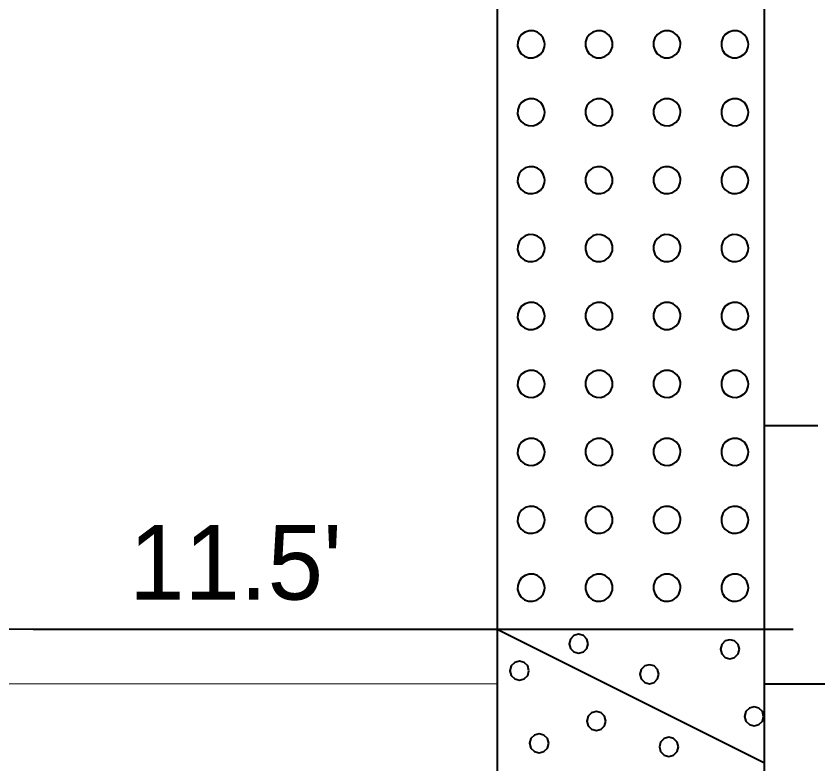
# Model space of a CAD drawing. Extents: x -76 to 974, y -1080 to -735.
# Drawn here: x 281.69 to 289.19, y -942.84 to -935.85 of the extents above; entities that cross this region are included whole.
import ezdxf

# ---------------------------------------------------------------- set-up
doc = ezdxf.new("R2010")
doc.units = 0
doc.header["$LTSCALE"] = 0.36
doc.linetypes.add('LONG_DASHED', pattern=[7.5, 6, -1.5])
for name, color, linetype, lineweight in [('27', 7, 'Continuous', 40), ('28', 7, 'LONG_DASHED', 60), ('7', 7, 'Continuous', 13)]:
    doc.layers.add(name, color=color, linetype=linetype, lineweight=lineweight)

msp = doc.modelspace()

# ---------------------------------------------------------------- linework, layer by layer
at = {"layer": '27'}
for p, q in [((286.1855, -930.0789), (286.1855, -941.5789)), ((288.6855, -941.5789), (288.6855, -930.0789)), ((289.1855, -939.6789), (288.6855, -939.6789)), ((282.4181, -941.5789), (286.1855, -941.5789)), ((286.1855, -941.5789), (288.6855, -941.5789)), ((286.1855, -941.5789), (288.6855, -942.8289)), ((286.1855, -941.5789), (286.1855, -947.0789)), ((288.6855, -947.0789), (288.6855, -941.5789)), ((288.6855, -942.09), (321.1855, -942.09))]:
    msp.add_line(p, q, dxfattribs=at)
for points in [[(286.6301, -936.1114), (286.6286, -936.0917), (286.6164, -936.054), (286.5933, -936.0219), (286.5614, -935.9985), (286.5239, -935.986), (286.4843, -935.9857), (286.4466, -935.9975), (286.4143, -936.0204), (286.3906, -936.0521), (286.3778, -936.0895), (286.3771, -936.129), (286.3886, -936.1669), (286.4112, -936.1994), (286.4426, -936.2233), (286.4799, -936.2365), (286.5195, -936.2375), (286.5574, -936.2263), (286.5901, -936.204), (286.6143, -936.1728), (286.6278, -936.1356)], [(287.2651, -936.1114), (287.2636, -936.0917), (287.2514, -936.054), (287.2283, -936.0219), (287.1964, -935.9985), (287.1589, -935.986), (287.1193, -935.9857), (287.0816, -935.9975), (287.0493, -936.0204), (287.0256, -936.0521), (287.0128, -936.0895), (287.0121, -936.129), (287.0236, -936.1669), (287.0462, -936.1994), (287.0776, -936.2233), (287.1149, -936.2365), (287.1545, -936.2375), (287.1924, -936.2263), (287.2251, -936.204), (287.2493, -936.1728), (287.2628, -936.1356)], [(287.9001, -936.1114), (287.8986, -936.0917), (287.8864, -936.054), (287.8633, -936.0219), (287.8314, -935.9985), (287.7939, -935.986), (287.7543, -935.9857), (287.7166, -935.9975), (287.6843, -936.0204), (287.6606, -936.0521), (287.6478, -936.0895), (287.6471, -936.129), (287.6586, -936.1669), (287.6812, -936.1994), (287.7126, -936.2233), (287.7499, -936.2365), (287.7895, -936.2375), (287.8274, -936.2263), (287.8601, -936.204), (287.8843, -936.1728), (287.8978, -936.1356)], [(288.5351, -936.1114), (288.5336, -936.0917), (288.5214, -936.054), (288.4983, -936.0219), (288.4664, -935.9985), (288.4289, -935.986), (288.3893, -935.9857), (288.3516, -935.9975), (288.3193, -936.0204), (288.2956, -936.0521), (288.2828, -936.0895), (288.2821, -936.129), (288.2936, -936.1669), (288.3162, -936.1994), (288.3476, -936.2233), (288.3849, -936.2365), (288.4245, -936.2375), (288.4624, -936.2263), (288.4951, -936.204), (288.5193, -936.1728), (288.5328, -936.1356)], [(286.6301, -936.7464), (286.6286, -936.7267), (286.6164, -936.689), (286.5933, -936.6569), (286.5614, -936.6335), (286.5239, -936.621), (286.4843, -936.6207), (286.4466, -936.6325), (286.4143, -936.6554), (286.3906, -936.6871), (286.3778, -936.7245), (286.3771, -936.764), (286.3886, -936.8019), (286.4112, -936.8344), (286.4426, -936.8583), (286.4799, -936.8715), (286.5195, -936.8725), (286.5574, -936.8613), (286.5901, -936.839), (286.6143, -936.8078), (286.6278, -936.7706)], [(287.2651, -936.7464), (287.2636, -936.7267), (287.2514, -936.689), (287.2283, -936.6569), (287.1964, -936.6335), (287.1589, -936.621), (287.1193, -936.6207), (287.0816, -936.6325), (287.0493, -936.6554), (287.0256, -936.6871), (287.0128, -936.7245), (287.0121, -936.764), (287.0236, -936.8019), (287.0462, -936.8344), (287.0776, -936.8583), (287.1149, -936.8715), (287.1545, -936.8725), (287.1924, -936.8613), (287.2251, -936.839), (287.2493, -936.8078), (287.2628, -936.7706)], [(287.9001, -936.7464), (287.8986, -936.7267), (287.8864, -936.689), (287.8633, -936.6569), (287.8314, -936.6335), (287.7939, -936.621), (287.7543, -936.6207), (287.7166, -936.6325), (287.6843, -936.6554), (287.6606, -936.6871), (287.6478, -936.7245), (287.6471, -936.764), (287.6586, -936.8019), (287.6812, -936.8344), (287.7126, -936.8583), (287.7499, -936.8715), (287.7895, -936.8725), (287.8274, -936.8613), (287.8601, -936.839), (287.8843, -936.8078), (287.8978, -936.7706)], [(288.5351, -936.7464), (288.5336, -936.7267), (288.5214, -936.689), (288.4983, -936.6569), (288.4664, -936.6335), (288.4289, -936.621), (288.3893, -936.6207), (288.3516, -936.6325), (288.3193, -936.6554), (288.2956, -936.6871), (288.2828, -936.7245), (288.2821, -936.764), (288.2936, -936.8019), (288.3162, -936.8344), (288.3476, -936.8583), (288.3849, -936.8715), (288.4245, -936.8725), (288.4624, -936.8613), (288.4951, -936.839), (288.5193, -936.8078), (288.5328, -936.7706)], [(286.6301, -937.3814), (286.6286, -937.3617), (286.6164, -937.324), (286.5933, -937.2919), (286.5614, -937.2685), (286.5239, -937.256), (286.4843, -937.2557), (286.4466, -937.2675), (286.4143, -937.2904), (286.3906, -937.3221), (286.3778, -937.3595), (286.3771, -937.399), (286.3886, -937.4369), (286.4112, -937.4694), (286.4426, -937.4933), (286.4799, -937.5065), (286.5195, -937.5075), (286.5574, -937.4963), (286.5901, -937.474), (286.6143, -937.4428), (286.6278, -937.4056)], [(287.2651, -937.3814), (287.2636, -937.3617), (287.2514, -937.324), (287.2283, -937.2919), (287.1964, -937.2685), (287.1589, -937.256), (287.1193, -937.2557), (287.0816, -937.2675), (287.0493, -937.2904), (287.0256, -937.3221), (287.0128, -937.3595), (287.0121, -937.399), (287.0236, -937.4369), (287.0462, -937.4694), (287.0776, -937.4933), (287.1149, -937.5065), (287.1545, -937.5075), (287.1924, -937.4963), (287.2251, -937.474), (287.2493, -937.4428), (287.2628, -937.4056)], [(287.9001, -937.3814), (287.8986, -937.3617), (287.8864, -937.324), (287.8633, -937.2919), (287.8314, -937.2685), (287.7939, -937.256), (287.7543, -937.2557), (287.7166, -937.2675), (287.6843, -937.2904), (287.6606, -937.3221), (287.6478, -937.3595), (287.6471, -937.399), (287.6586, -937.4369), (287.6812, -937.4694), (287.7126, -937.4933), (287.7499, -937.5065), (287.7895, -937.5075), (287.8274, -937.4963), (287.8601, -937.474), (287.8843, -937.4428), (287.8978, -937.4056)], [(288.5351, -937.3814), (288.5336, -937.3617), (288.5214, -937.324), (288.4983, -937.2919), (288.4664, -937.2685), (288.4289, -937.256), (288.3893, -937.2557), (288.3516, -937.2675), (288.3193, -937.2904), (288.2956, -937.3221), (288.2828, -937.3595), (288.2821, -937.399), (288.2936, -937.4369), (288.3162, -937.4694), (288.3476, -937.4933), (288.3849, -937.5065), (288.4245, -937.5075), (288.4624, -937.4963), (288.4951, -937.474), (288.5193, -937.4428), (288.5328, -937.4056)], [(286.6301, -938.0164), (286.6286, -937.9967), (286.6164, -937.959), (286.5933, -937.9269), (286.5614, -937.9035), (286.5239, -937.891), (286.4843, -937.8907), (286.4466, -937.9025), (286.4143, -937.9254), (286.3906, -937.9571), (286.3778, -937.9945), (286.3771, -938.034), (286.3886, -938.0719), (286.4112, -938.1044), (286.4426, -938.1283), (286.4799, -938.1415), (286.5195, -938.1425), (286.5574, -938.1313), (286.5901, -938.109), (286.6143, -938.0778), (286.6278, -938.0406)], [(287.2651, -938.0164), (287.2636, -937.9967), (287.2514, -937.959), (287.2283, -937.9269), (287.1964, -937.9035), (287.1589, -937.891), (287.1193, -937.8907), (287.0816, -937.9025), (287.0493, -937.9254), (287.0256, -937.9571), (287.0128, -937.9945), (287.0121, -938.034), (287.0236, -938.0719), (287.0462, -938.1044), (287.0776, -938.1283), (287.1149, -938.1415), (287.1545, -938.1425), (287.1924, -938.1313), (287.2251, -938.109), (287.2493, -938.0778), (287.2628, -938.0406)], [(287.9001, -938.0164), (287.8986, -937.9967), (287.8864, -937.959), (287.8633, -937.9269), (287.8314, -937.9035), (287.7939, -937.891), (287.7543, -937.8907), (287.7166, -937.9025), (287.6843, -937.9254), (287.6606, -937.9571), (287.6478, -937.9945), (287.6471, -938.034), (287.6586, -938.0719), (287.6812, -938.1044), (287.7126, -938.1283), (287.7499, -938.1415), (287.7895, -938.1425), (287.8274, -938.1313), (287.8601, -938.109), (287.8843, -938.0778), (287.8978, -938.0406)], [(288.5351, -938.0164), (288.5336, -937.9967), (288.5214, -937.959), (288.4983, -937.9269), (288.4664, -937.9035), (288.4289, -937.891), (288.3893, -937.8907), (288.3516, -937.9025), (288.3193, -937.9254), (288.2956, -937.9571), (288.2828, -937.9945), (288.2821, -938.034), (288.2936, -938.0719), (288.3162, -938.1044), (288.3476, -938.1283), (288.3849, -938.1415), (288.4245, -938.1425), (288.4624, -938.1313), (288.4951, -938.109), (288.5193, -938.0778), (288.5328, -938.0406)], [(286.6301, -938.6514), (286.6286, -938.6317), (286.6164, -938.594), (286.5933, -938.5619), (286.5614, -938.5385), (286.5239, -938.526), (286.4843, -938.5257), (286.4466, -938.5375), (286.4143, -938.5604), (286.3906, -938.5921), (286.3778, -938.6295), (286.3771, -938.669), (286.3886, -938.7069), (286.4112, -938.7394), (286.4426, -938.7633), (286.4799, -938.7765), (286.5195, -938.7775), (286.5574, -938.7663), (286.5901, -938.744), (286.6143, -938.7128), (286.6278, -938.6756)], [(287.2651, -938.6514), (287.2636, -938.6317), (287.2514, -938.594), (287.2283, -938.5619), (287.1964, -938.5385), (287.1589, -938.526), (287.1193, -938.5257), (287.0816, -938.5375), (287.0493, -938.5604), (287.0256, -938.5921), (287.0128, -938.6295), (287.0121, -938.669), (287.0236, -938.7069), (287.0462, -938.7394), (287.0776, -938.7633), (287.1149, -938.7765), (287.1545, -938.7775), (287.1924, -938.7663), (287.2251, -938.744), (287.2493, -938.7128), (287.2628, -938.6756)], [(287.9001, -938.6514), (287.8986, -938.6317), (287.8864, -938.594), (287.8633, -938.5619), (287.8314, -938.5385), (287.7939, -938.526), (287.7543, -938.5257), (287.7166, -938.5375), (287.6843, -938.5604), (287.6606, -938.5921), (287.6478, -938.6295), (287.6471, -938.669), (287.6586, -938.7069), (287.6812, -938.7394), (287.7126, -938.7633), (287.7499, -938.7765), (287.7895, -938.7775), (287.8274, -938.7663), (287.8601, -938.744), (287.8843, -938.7128), (287.8978, -938.6756)], [(288.5351, -938.6514), (288.5336, -938.6317), (288.5214, -938.594), (288.4983, -938.5619), (288.4664, -938.5385), (288.4289, -938.526), (288.3893, -938.5257), (288.3516, -938.5375), (288.3193, -938.5604), (288.2956, -938.5921), (288.2828, -938.6295), (288.2821, -938.669), (288.2936, -938.7069), (288.3162, -938.7394), (288.3476, -938.7633), (288.3849, -938.7765), (288.4245, -938.7775), (288.4624, -938.7663), (288.4951, -938.744), (288.5193, -938.7128), (288.5328, -938.6756)], [(286.6301, -939.2864), (286.6286, -939.2667), (286.6164, -939.229), (286.5933, -939.1969), (286.5614, -939.1735), (286.5239, -939.161), (286.4843, -939.1607), (286.4466, -939.1725), (286.4143, -939.1954), (286.3906, -939.2271), (286.3778, -939.2645), (286.3771, -939.304), (286.3886, -939.3419), (286.4112, -939.3744), (286.4426, -939.3983), (286.4799, -939.4115), (286.5195, -939.4125), (286.5574, -939.4013), (286.5901, -939.379), (286.6143, -939.3478), (286.6278, -939.3106)], [(287.2651, -939.2864), (287.2636, -939.2667), (287.2514, -939.229), (287.2283, -939.1969), (287.1964, -939.1735), (287.1589, -939.161), (287.1193, -939.1607), (287.0816, -939.1725), (287.0493, -939.1954), (287.0256, -939.2271), (287.0128, -939.2645), (287.0121, -939.304), (287.0236, -939.3419), (287.0462, -939.3744), (287.0776, -939.3983), (287.1149, -939.4115), (287.1545, -939.4125), (287.1924, -939.4013), (287.2251, -939.379), (287.2493, -939.3478), (287.2628, -939.3106)], [(287.9001, -939.2864), (287.8986, -939.2667), (287.8864, -939.229), (287.8633, -939.1969), (287.8314, -939.1735), (287.7939, -939.161), (287.7543, -939.1607), (287.7166, -939.1725), (287.6843, -939.1954), (287.6606, -939.2271), (287.6478, -939.2645), (287.6471, -939.304), (287.6586, -939.3419), (287.6812, -939.3744), (287.7126, -939.3983), (287.7499, -939.4115), (287.7895, -939.4125), (287.8274, -939.4013), (287.8601, -939.379), (287.8843, -939.3478), (287.8978, -939.3106)], [(288.5351, -939.2864), (288.5336, -939.2667), (288.5214, -939.229), (288.4983, -939.1969), (288.4664, -939.1735), (288.4289, -939.161), (288.3893, -939.1607), (288.3516, -939.1725), (288.3193, -939.1954), (288.2956, -939.2271), (288.2828, -939.2645), (288.2821, -939.304), (288.2936, -939.3419), (288.3162, -939.3744), (288.3476, -939.3983), (288.3849, -939.4115), (288.4245, -939.4125), (288.4624, -939.4013), (288.4951, -939.379), (288.5193, -939.3478), (288.5328, -939.3106)], [(286.6301, -939.9214), (286.6286, -939.9017), (286.6164, -939.864), (286.5933, -939.8319), (286.5614, -939.8085), (286.5239, -939.796), (286.4843, -939.7957), (286.4466, -939.8075), (286.4143, -939.8304), (286.3906, -939.8621), (286.3778, -939.8995), (286.3771, -939.939), (286.3886, -939.9769), (286.4112, -940.0094), (286.4426, -940.0333), (286.4799, -940.0465), (286.5195, -940.0475), (286.5574, -940.0363), (286.5901, -940.014), (286.6143, -939.9828), (286.6278, -939.9456)], [(287.2651, -939.9214), (287.2636, -939.9017), (287.2514, -939.864), (287.2283, -939.8319), (287.1964, -939.8085), (287.1589, -939.796), (287.1193, -939.7957), (287.0816, -939.8075), (287.0493, -939.8304), (287.0256, -939.8621), (287.0128, -939.8995), (287.0121, -939.939), (287.0236, -939.9769), (287.0462, -940.0094), (287.0776, -940.0333), (287.1149, -940.0465), (287.1545, -940.0475), (287.1924, -940.0363), (287.2251, -940.014), (287.2493, -939.9828), (287.2628, -939.9456)], [(287.9001, -939.9214), (287.8986, -939.9017), (287.8864, -939.864), (287.8633, -939.8319), (287.8314, -939.8085), (287.7939, -939.796), (287.7543, -939.7957), (287.7166, -939.8075), (287.6843, -939.8304), (287.6606, -939.8621), (287.6478, -939.8995), (287.6471, -939.939), (287.6586, -939.9769), (287.6812, -940.0094), (287.7126, -940.0333), (287.7499, -940.0465), (287.7895, -940.0475), (287.8274, -940.0363), (287.8601, -940.014), (287.8843, -939.9828), (287.8978, -939.9456)], [(288.5351, -939.9214), (288.5336, -939.9017), (288.5214, -939.864), (288.4983, -939.8319), (288.4664, -939.8085), (288.4289, -939.796), (288.3893, -939.7957), (288.3516, -939.8075), (288.3193, -939.8304), (288.2956, -939.8621), (288.2828, -939.8995), (288.2821, -939.939), (288.2936, -939.9769), (288.3162, -940.0094), (288.3476, -940.0333), (288.3849, -940.0465), (288.4245, -940.0475), (288.4624, -940.0363), (288.4951, -940.014), (288.5193, -939.9828), (288.5328, -939.9456)], [(286.6301, -940.5564), (286.6286, -940.5367), (286.6164, -940.499), (286.5933, -940.4669), (286.5614, -940.4435), (286.5239, -940.431), (286.4843, -940.4307), (286.4466, -940.4425), (286.4143, -940.4654), (286.3906, -940.4971), (286.3778, -940.5345), (286.3771, -940.574), (286.3886, -940.6119), (286.4112, -940.6444), (286.4426, -940.6683), (286.4799, -940.6815), (286.5195, -940.6825), (286.5574, -940.6713), (286.5901, -940.649), (286.6143, -940.6178), (286.6278, -940.5806)], [(287.2651, -940.5564), (287.2636, -940.5367), (287.2514, -940.499), (287.2283, -940.4669), (287.1964, -940.4435), (287.1589, -940.431), (287.1193, -940.4307), (287.0816, -940.4425), (287.0493, -940.4654), (287.0256, -940.4971), (287.0128, -940.5345), (287.0121, -940.574), (287.0236, -940.6119), (287.0462, -940.6444), (287.0776, -940.6683), (287.1149, -940.6815), (287.1545, -940.6825), (287.1924, -940.6713), (287.2251, -940.649), (287.2493, -940.6178), (287.2628, -940.5806)], [(287.9001, -940.5564), (287.8986, -940.5367), (287.8864, -940.499), (287.8633, -940.4669), (287.8314, -940.4435), (287.7939, -940.431), (287.7543, -940.4307), (287.7166, -940.4425), (287.6843, -940.4654), (287.6606, -940.4971), (287.6478, -940.5345), (287.6471, -940.574), (287.6586, -940.6119), (287.6812, -940.6444), (287.7126, -940.6683), (287.7499, -940.6815), (287.7895, -940.6825), (287.8274, -940.6713), (287.8601, -940.649), (287.8843, -940.6178), (287.8978, -940.5806)], [(288.5351, -940.5564), (288.5336, -940.5367), (288.5214, -940.499), (288.4983, -940.4669), (288.4664, -940.4435), (288.4289, -940.431), (288.3893, -940.4307), (288.3516, -940.4425), (288.3193, -940.4654), (288.2956, -940.4971), (288.2828, -940.5345), (288.2821, -940.574), (288.2936, -940.6119), (288.3162, -940.6444), (288.3476, -940.6683), (288.3849, -940.6815), (288.4245, -940.6825), (288.4624, -940.6713), (288.4951, -940.649), (288.5193, -940.6178), (288.5328, -940.5806)], [(286.6301, -941.1914), (286.6286, -941.1717), (286.6164, -941.134), (286.5933, -941.1019), (286.5614, -941.0785), (286.5239, -941.066), (286.4843, -941.0657), (286.4466, -941.0775), (286.4143, -941.1004), (286.3906, -941.1321), (286.3778, -941.1695), (286.3771, -941.209), (286.3886, -941.2469), (286.4112, -941.2794), (286.4426, -941.3033), (286.4799, -941.3165), (286.5195, -941.3175), (286.5574, -941.3063), (286.5901, -941.284), (286.6143, -941.2528), (286.6278, -941.2156)], [(287.2651, -941.1914), (287.2636, -941.1717), (287.2514, -941.134), (287.2283, -941.1019), (287.1964, -941.0785), (287.1589, -941.066), (287.1193, -941.0657), (287.0816, -941.0775), (287.0493, -941.1004), (287.0256, -941.1321), (287.0128, -941.1695), (287.0121, -941.209), (287.0236, -941.2469), (287.0462, -941.2794), (287.0776, -941.3033), (287.1149, -941.3165), (287.1545, -941.3175), (287.1924, -941.3063), (287.2251, -941.284), (287.2493, -941.2528), (287.2628, -941.2156)], [(287.9001, -941.1914), (287.8986, -941.1717), (287.8864, -941.134), (287.8633, -941.1019), (287.8314, -941.0785), (287.7939, -941.066), (287.7543, -941.0657), (287.7166, -941.0775), (287.6843, -941.1004), (287.6606, -941.1321), (287.6478, -941.1695), (287.6471, -941.209), (287.6586, -941.2469), (287.6812, -941.2794), (287.7126, -941.3033), (287.7499, -941.3165), (287.7895, -941.3175), (287.8274, -941.3063), (287.8601, -941.284), (287.8843, -941.2528), (287.8978, -941.2156)], [(288.5351, -941.1914), (288.5336, -941.1717), (288.5214, -941.134), (288.4983, -941.1019), (288.4664, -941.0785), (288.4289, -941.066), (288.3893, -941.0657), (288.3516, -941.0775), (288.3193, -941.1004), (288.2956, -941.1321), (288.2828, -941.1695), (288.2821, -941.209), (288.2936, -941.2469), (288.3162, -941.2794), (288.3476, -941.3033), (288.3849, -941.3165), (288.4245, -941.3175), (288.4624, -941.3063), (288.4951, -941.284), (288.5193, -941.2528), (288.5328, -941.2156)], [(287.0362, -941.7152), (287.0243, -941.6708), (286.9917, -941.6383), (286.9473, -941.6263), (286.9028, -941.6383), (286.8703, -941.6708), (286.8584, -941.7152), (286.8703, -941.7597), (286.9028, -941.7922), (286.9473, -941.8041), (286.9917, -941.7922), (287.0243, -941.7597)], [(288.451, -941.7662), (288.4391, -941.7217), (288.4066, -941.6892), (288.3621, -941.6773), (288.3177, -941.6892), (288.2851, -941.7217), (288.2732, -941.7662), (288.2851, -941.8106), (288.3177, -941.8432), (288.3621, -941.8551), (288.4066, -941.8432), (288.4391, -941.8106)], [(286.4831, -941.967), (286.4712, -941.9226), (286.4386, -941.89), (286.3942, -941.8781), (286.3497, -941.89), (286.3172, -941.9226), (286.3053, -941.967), (286.3172, -942.0115), (286.3497, -942.044), (286.3942, -942.0559), (286.4386, -942.044), (286.4712, -942.0115)], [(287.6984, -942.0001), (287.6865, -941.9556), (287.654, -941.9231), (287.6095, -941.9112), (287.5651, -941.9231), (287.5325, -941.9556), (287.5206, -942.0001), (287.5325, -942.0445), (287.5651, -942.0771), (287.6095, -942.089), (287.654, -942.0771), (287.6865, -942.0445)], [(288.6773, -942.3942), (288.6654, -942.3497), (288.6329, -942.3172), (288.5884, -942.3053), (288.544, -942.3172), (288.5114, -942.3497), (288.4995, -942.3942), (288.5114, -942.4386), (288.544, -942.4712), (288.5884, -942.4831), (288.6329, -942.4712), (288.6654, -942.4386)], [(287.2026, -942.4374), (287.1907, -942.393), (287.1582, -942.3604), (287.1137, -942.3485), (287.0693, -942.3604), (287.0367, -942.393), (287.0248, -942.4374), (287.0367, -942.4819), (287.0693, -942.5144), (287.1137, -942.5263), (287.1582, -942.5144), (287.1907, -942.4819)], [(286.6674, -942.6459), (286.6555, -942.6014), (286.623, -942.5689), (286.5785, -942.557), (286.5341, -942.5689), (286.5015, -942.6014), (286.4896, -942.6459), (286.5015, -942.6903), (286.5341, -942.7229), (286.5785, -942.7348), (286.623, -942.7229), (286.6555, -942.6903)], [(287.8802, -942.6789), (287.8683, -942.6345), (287.8358, -942.602), (287.7913, -942.59), (287.7469, -942.602), (287.7143, -942.6345), (287.7024, -942.6789), (287.7143, -942.7234), (287.7469, -942.7559), (287.7913, -942.7678), (287.8358, -942.7559), (287.8683, -942.7234)]]:
    msp.add_lwpolyline(points, close=True, dxfattribs=at)
at = {"layer": '28', "lineweight": 40}
msp.add_spline([(273.2952, -941.5241), (282.4181, -941.5789), (286.1855, -941.5789), (288.6855, -941.5789), (305.5141, -941.5789)], degree=3, dxfattribs=at)
at = {"layer": '7'}
msp.add_line((256.2421, -942.09), (286.1855, -942.09), dxfattribs=at)

# ---------------------------------------------------------------- texts
at = {"layer": '27'}
msp.add_text("11.5'", height=0.6976, dxfattribs=at).set_placement((282.7421, -941.3025))

doc.saveas('drawing.dxf')
